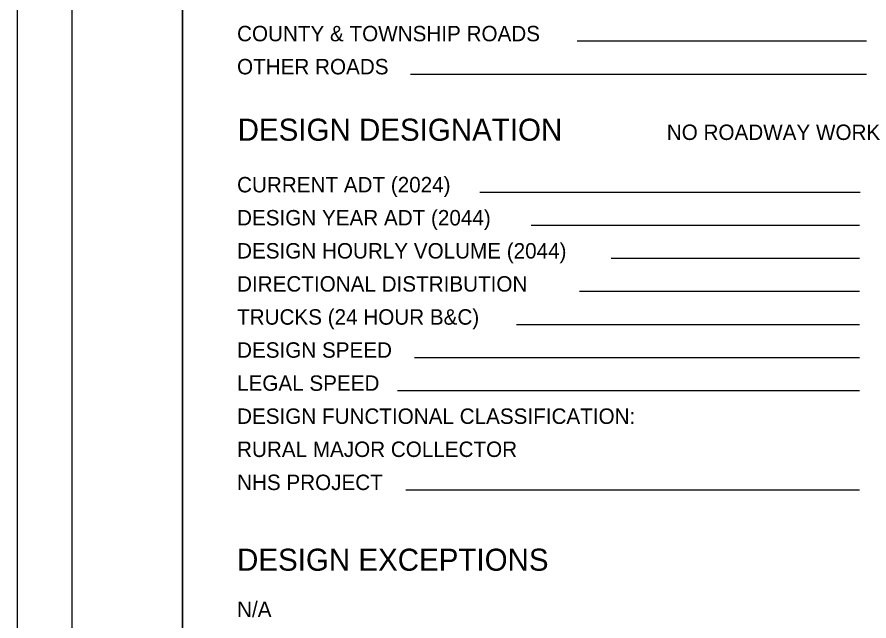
# Model space of a CAD drawing. Extents: x 0 to 84, y -106 to 22.
# Drawn here: x 0 to 7.72, y 5.43 to 10.9 of the extents above; entities that cross this region are included whole.
import ezdxf

# ---------------------------------------------------------------- set-up
doc = ezdxf.new("R2010")
doc.units = 0
for name, color, linetype in [('CS-ALGN-CNTR', 7, 'Continuous'), ('CS-ALGN-TEXT', 7, 'Continuous'), ('CS-ANNO', 7, 'Continuous'), ('CS-ANNO-MATC', 7, 'Continuous')]:
    doc.layers.add(name, color=color, linetype=linetype)

msp = doc.modelspace()

# ---------------------------------------------------------------- linework, layer by layer
at = {"layer": 'CS-ALGN-CNTR'}
msp.add_lwpolyline([(0, 0), (34, 0), (34, 22), (0, 22)], close=True, dxfattribs=at)
at = {"layer": 'CS-ALGN-TEXT'}
for points in [[(0.5, 21.5), (1.5, 21.5), (1.5, 0.5), (0.5, 0.5)], [(1.5, 21.5), (33.5, 21.5), (33.5, 0.5), (1.5, 0.5)]]:
    msp.add_lwpolyline(points, close=True, dxfattribs=at)
at = {"layer": 'CS-ANNO'}
for p, q in [((7.7, 10.6848), (5.0782, 10.6848)), ((7.7, 10.3848), (3.5657, 10.3848)), ((7.6424, 9.3144), (4.1936, 9.3144)), ((7.6368, 9.0144), (4.6592, 9.0144)), ((7.6368, 8.7144), (5.3852, 8.7144)), ((7.6368, 8.4144), (5.0988, 8.4144)), ((7.6368, 8.1144), (4.5259, 8.1144)), ((7.6368, 7.8144), (3.6035, 7.8144)), ((7.6368, 7.5144), (3.4488, 7.5144)), ((7.6368, 6.6144), (3.5243, 6.6144))]:
    msp.add_line(p, q, dxfattribs=at)

# ---------------------------------------------------------------- texts
msp.add_text('DESIGN DESIGNATION', height=0.2, dxfattribs=at).set_placement((2, 9.7828))
at = {"layer": 'CS-ANNO-MATC'}
for s, height, p in [('COUNTY & TOWNSHIP ROADS', 0.14, (1.9944, 10.6848)), ('OTHER ROADS', 0.14, (1.9944, 10.3848)), ('NO ROADWAY WORK', 0.14, (5.8897, 9.7897)), ('CURRENT ADT (2024)', 0.14, (1.9944, 9.3144)), ('DESIGN YEAR ADT (2044)', 0.14, (1.9944, 9.0144)), ('DESIGN HOURLY VOLUME (2044)', 0.14, (1.9944, 8.7144)), ('DIRECTIONAL DISTRIBUTION', 0.14, (1.9944, 8.4144)), ('TRUCKS (24 HOUR B&C)', 0.14, (1.9944, 8.1144)), ('DESIGN SPEED', 0.14, (1.9944, 7.8144)), ('LEGAL SPEED', 0.14, (1.9944, 7.5144)), ('DESIGN FUNCTIONAL CLASSIFICATION:', 0.14, (1.9944, 7.2144)), ('RURAL MAJOR COLLECTOR', 0.14, (1.9944, 6.9144)), ('NHS PROJECT', 0.14, (1.9944, 6.6144)), ('DESIGN EXCEPTIONS', 0.2, (1.9944, 5.8826)), ('N/A', 0.14, (1.9944, 5.4626))]:
    msp.add_text(s, height=height, dxfattribs=at).set_placement(p)

doc.saveas('drawing.dxf')
